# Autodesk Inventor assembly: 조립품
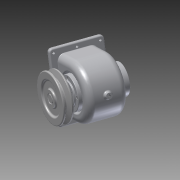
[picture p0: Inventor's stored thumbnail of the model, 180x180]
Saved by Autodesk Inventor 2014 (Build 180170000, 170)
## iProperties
Created: 2015-09
Part Number: 조립품
Document SubType Name: Assembly
Designer: Owner
Author: Owner
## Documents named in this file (13)
- C:\Documents and Settings\Owner\바탕 화면\450907V1024\조립품.iam
- C:\Documents and Settings\Owner\바탕 화면\450907V1024\축.ipt
- C:\Documents and Settings\Owner\바탕 화면\450907V1024\키 - 5 x 5 x 18.ipt
- C:\Documents and Settings\Owner\바탕 화면\450907V1024\키 - 6 x 6 x 22.ipt
- C:\Documents and Settings\Owner\바탕 화면\450907V1024\베어링 6203.ipt
- C:\Documents and Settings\Owner\바탕 화면\450907V1024\본체.ipt
- C:\Documents and Settings\Owner\바탕 화면\450907V1024\뒤커버.ipt
- C:\Documents and Settings\Owner\바탕 화면\450907V1024\앞커버.ipt
- C:\Documents and Settings\Owner\바탕 화면\450907V1024\오일 실 17 32 8.ipt
- C:\Documents and Settings\Owner\바탕 화면\450907V1024\스퍼기어.ipt
- C:\Documents and Settings\Owner\바탕 화면\450907V1024\V-벨트풀리.ipt
- C:\Documents and Settings\Owner\바탕 화면\450907V1024\멈춤나사 - M4x10.ipt
- C:\Documents and Settings\Owner\바탕 화면\450907V1024\볼트 M3 x 8.ipt
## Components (9 placed, 2 different names)
1. V-벨트풀리:1
2. ISO 4762 M3 x 8:2
3. ISO 4762 M3 x 8:1
4. ISO 4762 M3 x 8:3
5. ISO 4762 M3 x 8:4
6. ISO 4762 M3 x 8:5
7. ISO 4762 M3 x 8:6
8. ISO 4762 M3 x 8:7
9. ISO 4762 M3 x 8:8
